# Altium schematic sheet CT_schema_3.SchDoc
size 513 x 378 mm
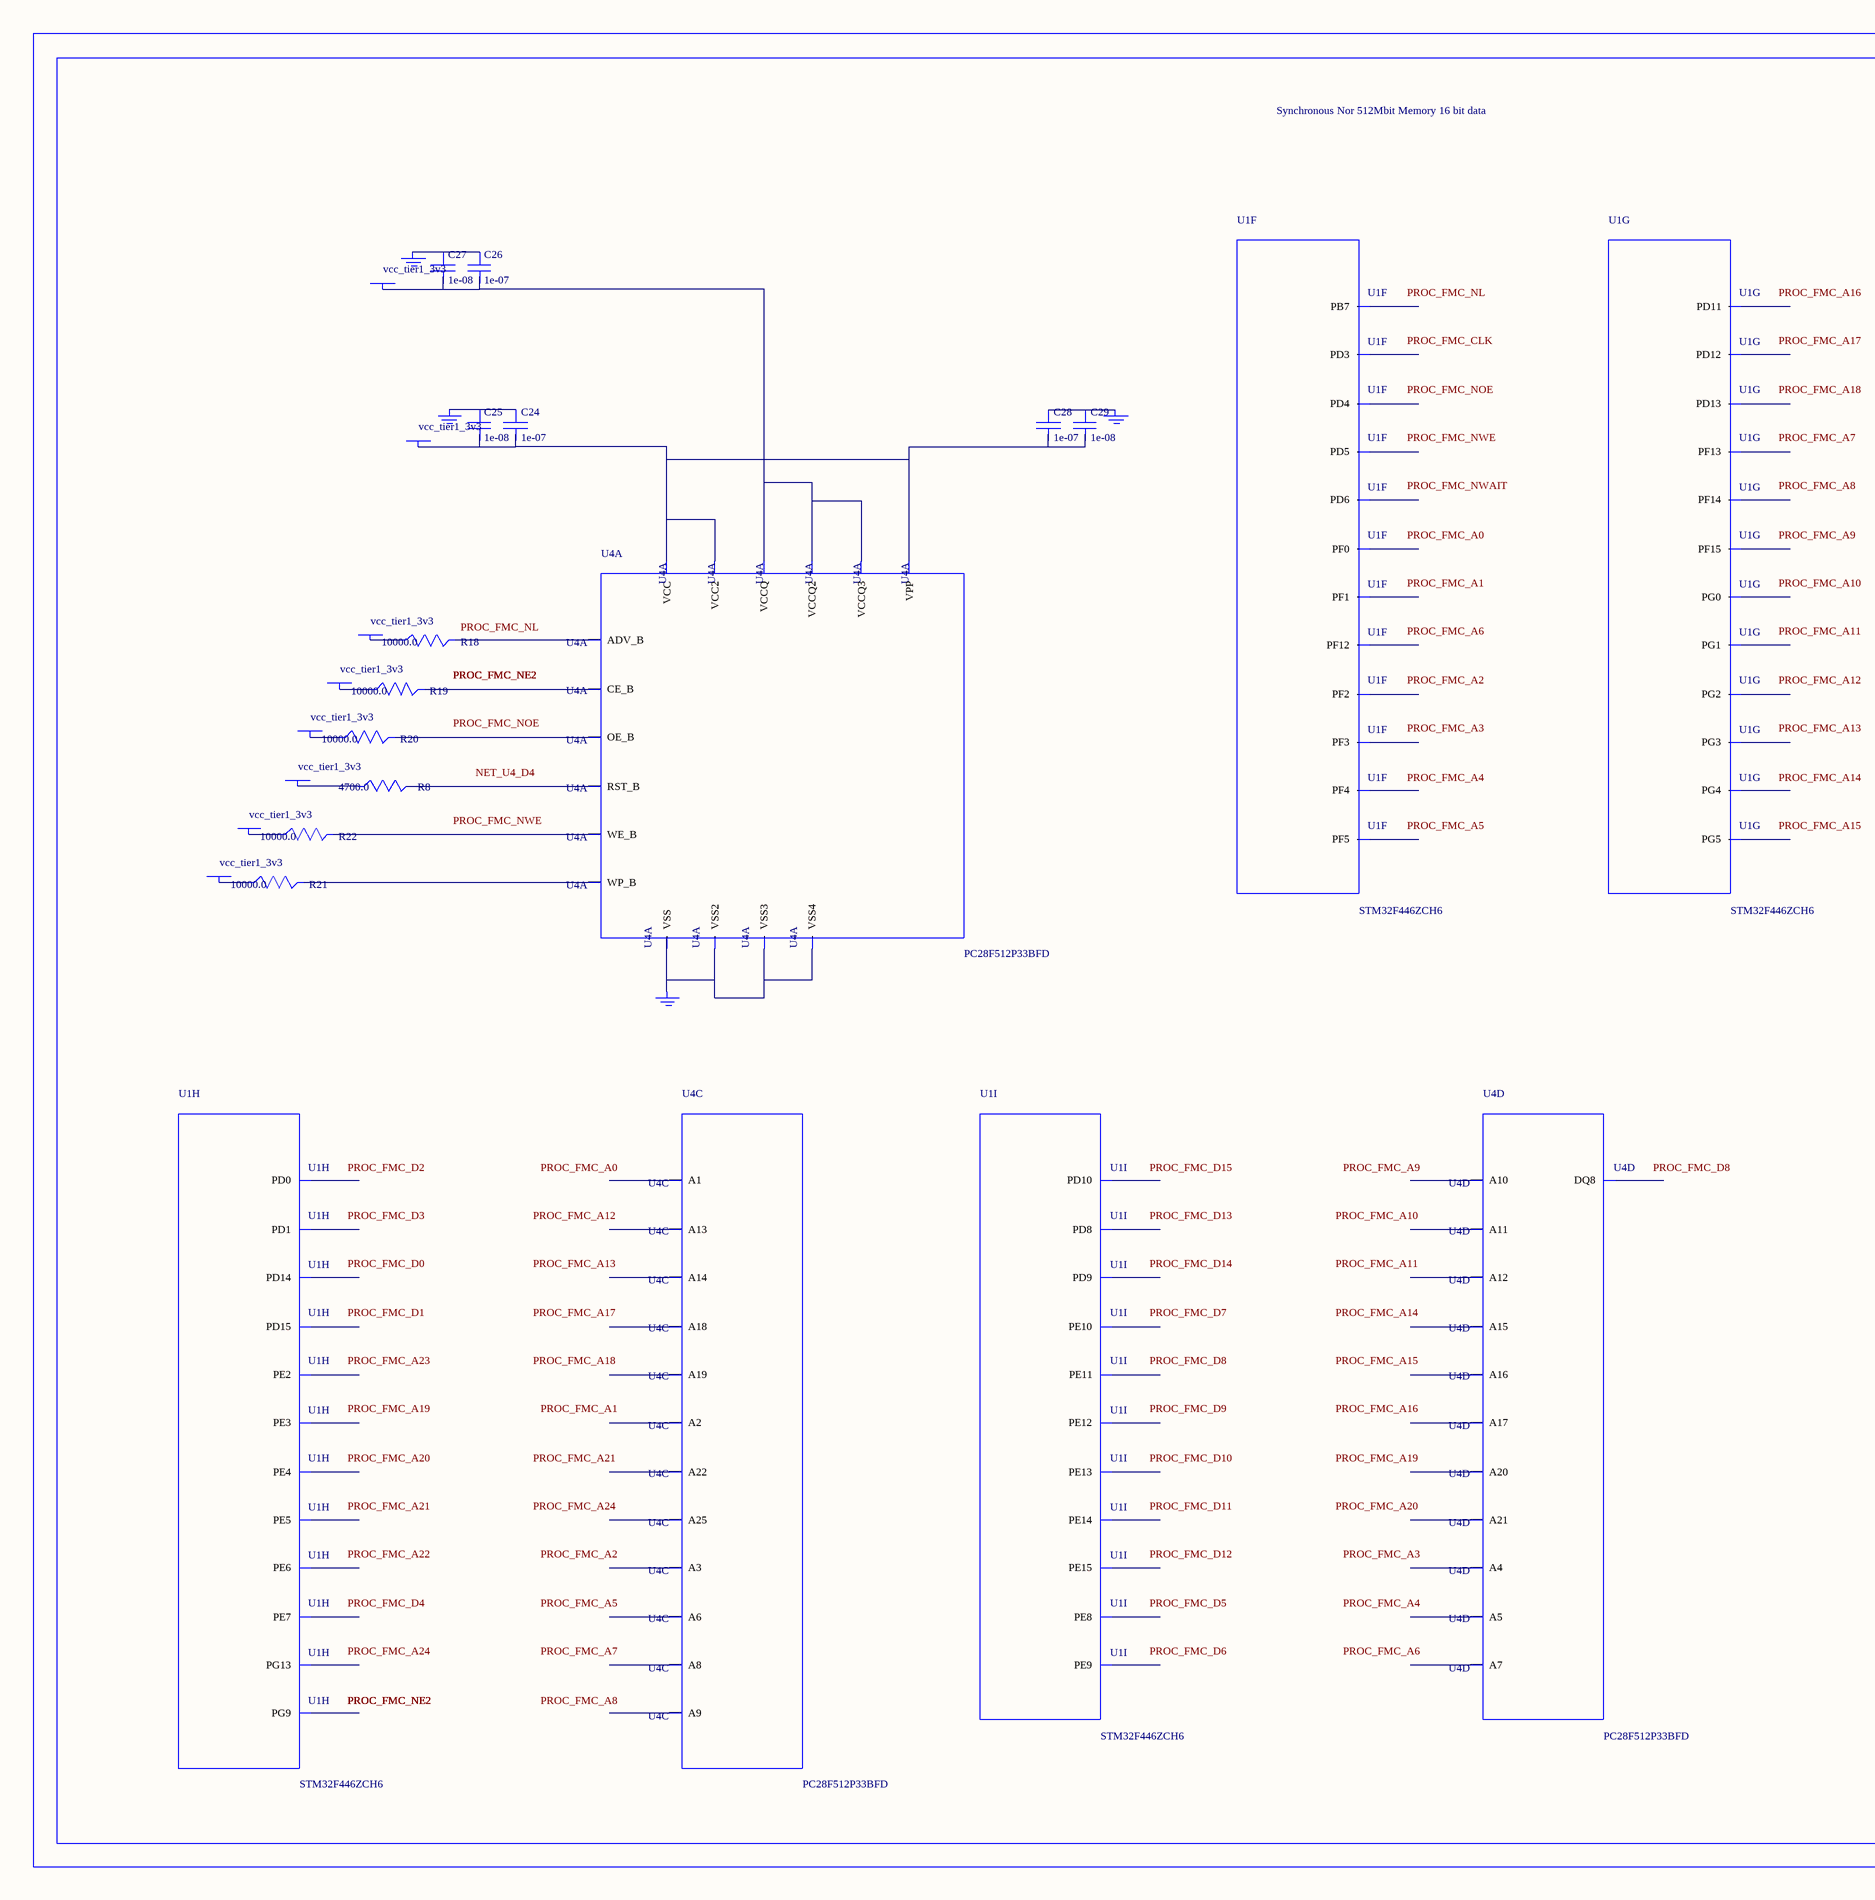
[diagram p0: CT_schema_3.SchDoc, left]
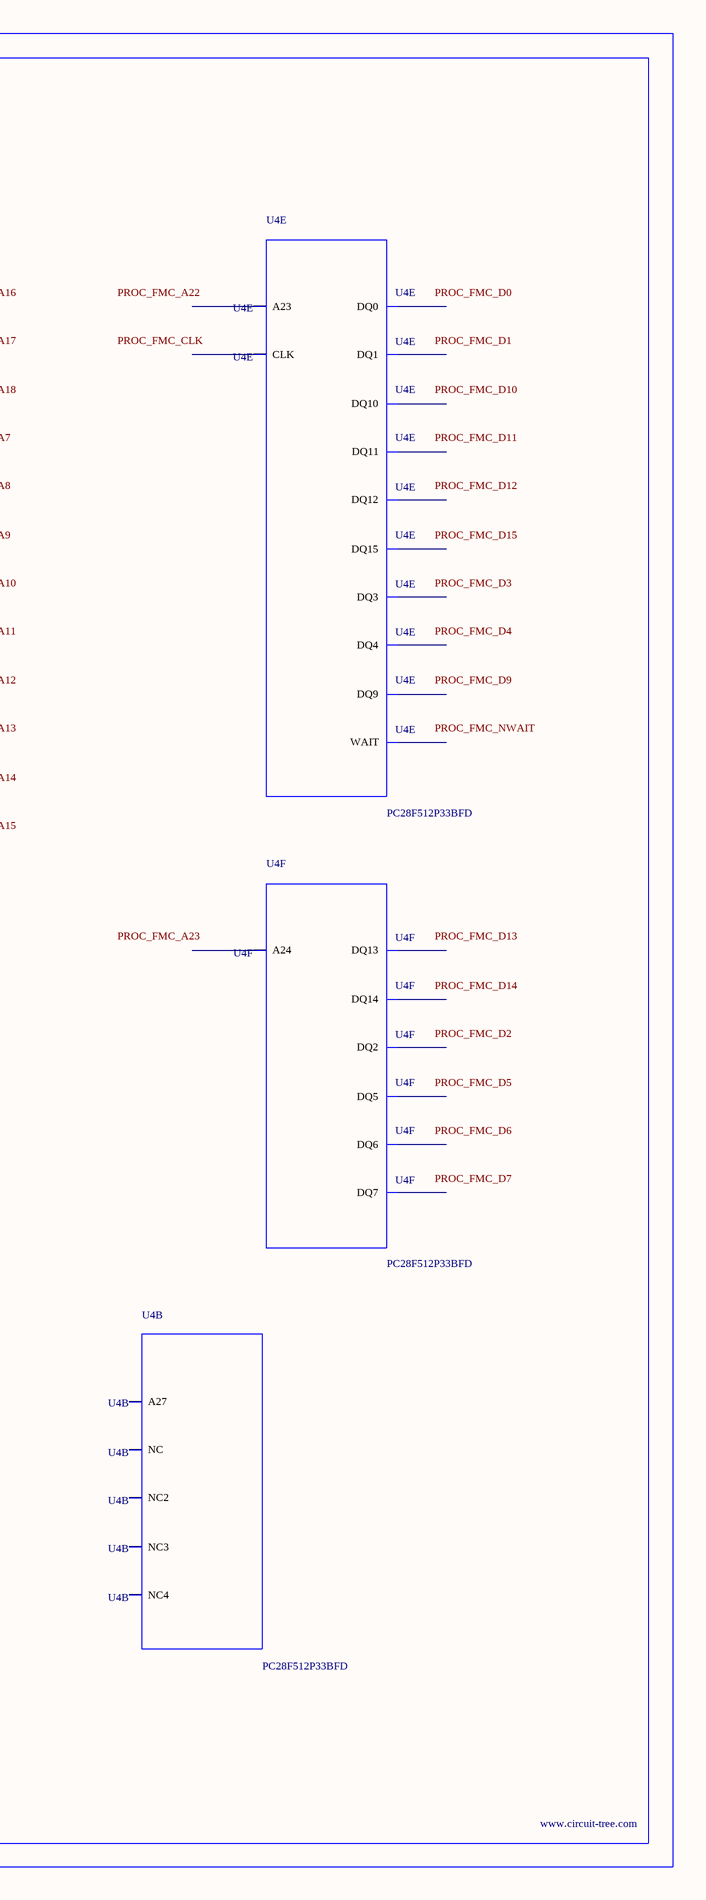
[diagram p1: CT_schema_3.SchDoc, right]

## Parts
BORDER2  (no value)
C24  1e-07  [C0402]
C25  1e-08  [C0402]
C26  1e-07  [C0402]
C27  1e-08  [C0402]
C28  1e-07  [C0402]
C29  1e-08  [C0402]
GND_INSTANCE_2_0  (no value)
GND_INSTANCE_2_1  (no value)
GND_INSTANCE_2_2  (no value)
GND_INSTANCE_2_3  (no value)
POWER_INSTANCE_2_0  vcc_tier1_3v3
POWER_INSTANCE_2_1  vcc_tier1_3v3
POWER_INSTANCE_2_2  vcc_tier1_3v3
POWER_INSTANCE_2_3  vcc_tier1_3v3
POWER_INSTANCE_2_4  vcc_tier1_3v3
POWER_INSTANCE_2_5  vcc_tier1_3v3
POWER_INSTANCE_2_6  vcc_tier1_3v3
POWER_INSTANCE_2_7  vcc_tier1_3v3
R8  4700.0  [R0603]
R18  10000.0  [R0603]
R19  10000.0  [R0603]
R20  10000.0  [R0603]
R21  10000.0  [R0603]
R22  10000.0  [R0603]
U1  STM32F446ZCH6  [UFBGA144]  (parts F,G,H,I of 11)
U4  PC28F512P33BFD  [PC28F512P33BFD]  (parts A,B,C,D,E,F of 6)

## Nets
NetC24_1: C24.1 C25.1 GND_INSTANCE_2_0.0(GND)
NetC24_2: C24.2 C25.2 C28.2 C29.2 POWER_INSTANCE_2_0.0(PWR) U4.A4(VPP) U4.A6(VCC) U4.H3(VCC2)
NetC26_1: C26.1 C27.1 GND_INSTANCE_2_1.0(GND)
NetC26_2: C26.2 C27.2 POWER_INSTANCE_2_1.0(PWR) U4.D5(VCCQ) U4.D6(VCCQ2) U4.G4(VCCQ3)
NetC28_1: C28.1 C29.1 GND_INSTANCE_2_2.0(GND)
NetGND_INSTANCE_2_3_0: GND_INSTANCE_2_3.0(GND) U4.B2(VSS) U4.H2(VSS2) U4.H4(VSS3) U4.H6(VSS4)
NetPOWER_INSTANCE_2_2_0: POWER_INSTANCE_2_2.0(PWR) R18.1
NetPOWER_INSTANCE_2_3_0: POWER_INSTANCE_2_3.0(PWR) R19.1
NetPOWER_INSTANCE_2_4_0: POWER_INSTANCE_2_4.0(PWR) R20.1
NetPOWER_INSTANCE_2_5_0: POWER_INSTANCE_2_5.0(PWR) R21.1
NetPOWER_INSTANCE_2_6_0: POWER_INSTANCE_2_6.0(PWR) R22.1
NetPOWER_INSTANCE_2_7_0: POWER_INSTANCE_2_7.0(PWR) R8.1
NetR8_2: R8.2 U4.D4(RST_B)
NetR18_2: R18.2 U4.F6(ADV_B)
NetR19_2: R19.2 U4.B4(CE_B)
NetR20_2: R20.2 U4.F8(OE_B)
NetR21_2: R21.2 U4.C6(WP_B)
NetR22_2: R22.2 U4.G8(WE_B)

Not connected (* = marked no-connect by the designer): U1 A2(PE3) A3(PE2) A8(PD6) B2(PE4) B3(PE5) B4(PE6) B9(PD5) C3(PF0) C4(PF1) C9(PD4) D4(PF2) D6(PB7) D7(PG13) D9(PD3) D10(PD1) E2(PF3) E3(PF4) E4(PF5) E8(PG9) E10(PD0) H8(PE11) H9(PD11) H12(PG5) J6(PG1) J7(PE10) J8(PE12) J9(PD10) J10(PG4) J11(PG3) J12(PG2) K5(PF13) K6(PG0) K7(PE9) K8(PE13) K9(PD9) K10(PD13) K11(PD14) K12(PD15) L5(PF12) L6(PF15) L7(PE8) L8(PE14) L9(PD8) L10(PD12) M6(PF14) M7(PE7) M8(PE15); U4 A1 A2(A6) A3(A8) A5(A13) A7(A18) A8(A22) B1(A2) B3(A9) B5(A14) B6(A25) B7(A19) B8(NC) C1(A3) C2(A7) C3(A10) C4(A12) C5(A15) C7(A20) C8(A21) D1(A4) D2(A5) D3(A11) D7(A16) D8(A17) E1(DQ8) E2(DQ1) E3(DQ9) E4(DQ3) E5(DQ4) E6(CLK) E7(DQ15) E8(NC2) F1(NC3) F2(DQ0) F3(DQ10) F4(DQ11) F5(DQ12) F7(WAIT) G1(A23) G2(NC4) G3(DQ2) G5(DQ5) G6(DQ6) G7(DQ14) H1(A27) H5(DQ13) H7(DQ7) H8(A24)

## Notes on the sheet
- Labels drawn without touching a wire or pin: NET_U4_D4, PROC_FMC_A0, PROC_FMC_A1, PROC_FMC_A2, PROC_FMC_A3, PROC_FMC_A4, PROC_FMC_A5, PROC_FMC_A6, PROC_FMC_A7, PROC_FMC_A8, PROC_FMC_A9, PROC_FMC_A10, PROC_FMC_A11, PROC_FMC_A12, PROC_FMC_A13, PROC_FMC_A14, PROC_FMC_A15, PROC_FMC_A16, PROC_FMC_A17, PROC_FMC_A18, PROC_FMC_A19, PROC_FMC_A20, PROC_FMC_A21, PROC_FMC_A22, PROC_FMC_A23, PROC_FMC_A24, PROC_FMC_CLK, PROC_FMC_D0, PROC_FMC_D1, PROC_FMC_D2, PROC_FMC_D3, PROC_FMC_D4, PROC_FMC_D5, PROC_FMC_D6, PROC_FMC_D7, PROC_FMC_D8, PROC_FMC_D9, PROC_FMC_D10, PROC_FMC_D11, PROC_FMC_D12, PROC_FMC_D13, PROC_FMC_D14, PROC_FMC_D15, PROC_FMC_NL, PROC_FMC_NOE, PROC_FMC_NWAIT, PROC_FMC_NWE

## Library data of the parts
BORDER2 = BORDER_PAGE2
C24 C26 C28 = C0402C104K3RACTU
C25 C27 C29 = C0402C103K3RAC
GND_INSTANCE_2_0-GND_INSTANCE_2_3 = GND
POWER_INSTANCE_2_0-POWER_INSTANCE_2_7 = PWR
R8 = RC0603JR-074K7L
R18-R22 = RC0603JR-0710KL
